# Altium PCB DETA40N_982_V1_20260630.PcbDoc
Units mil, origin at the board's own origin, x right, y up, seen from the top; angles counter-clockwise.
Board outline 2056.99 x 1054.68 mil, 4 copper layers (Top Layer, Layer 2, Layer 3, Bottom Layer), stack 62.681 mil thick; 56 components, 46 nets, 267 pads, 296 vias.
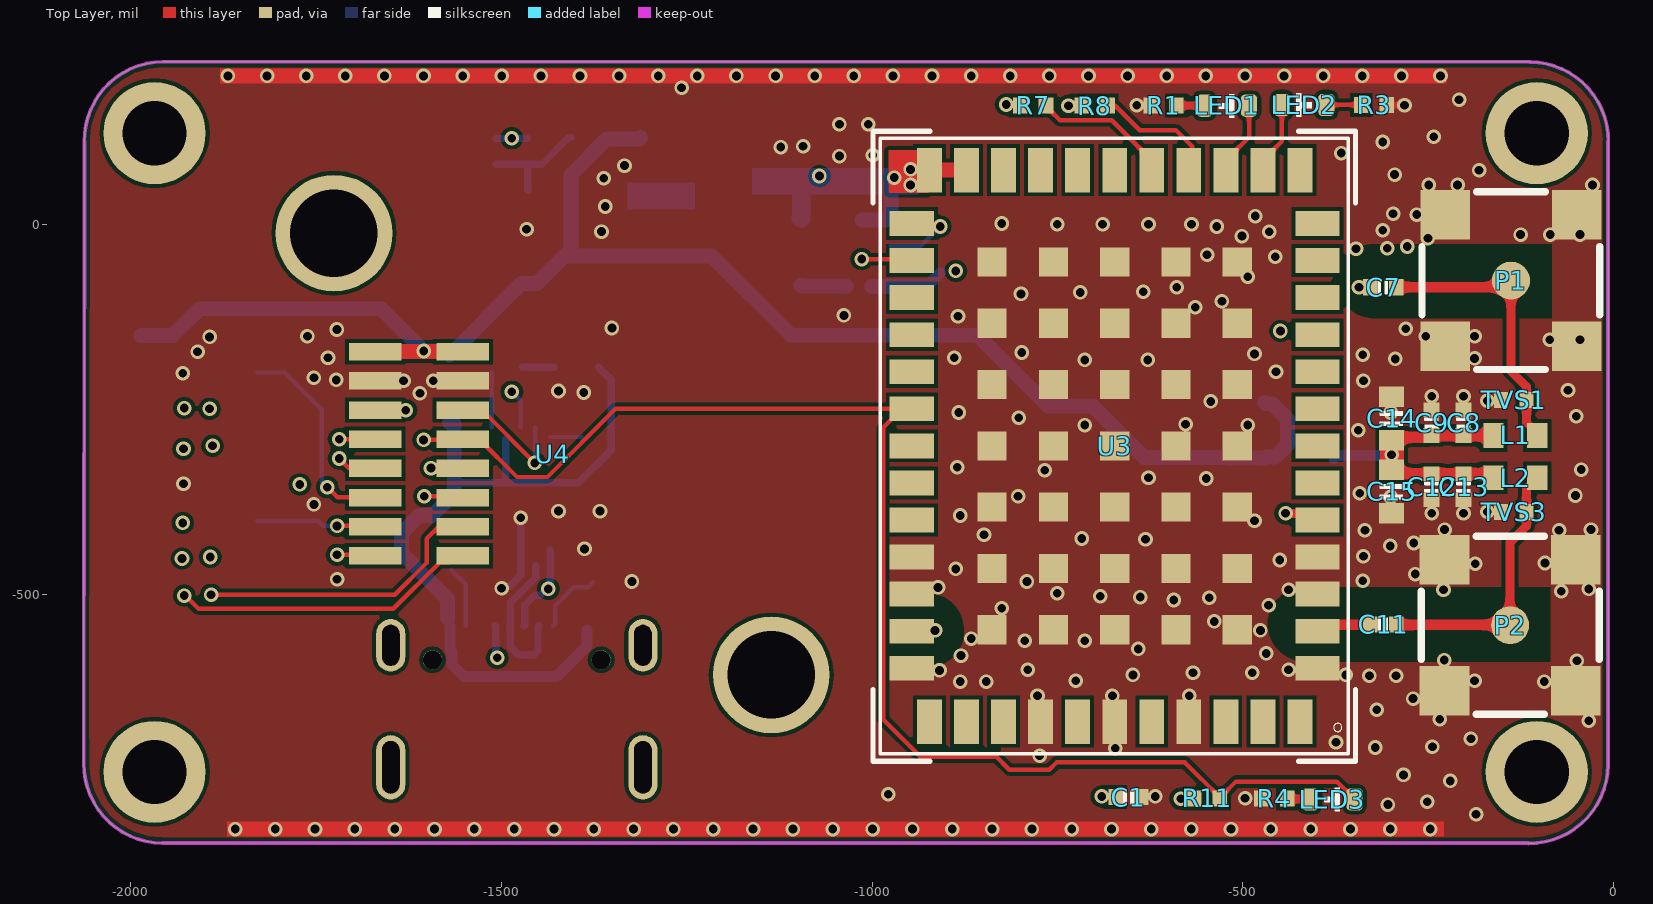
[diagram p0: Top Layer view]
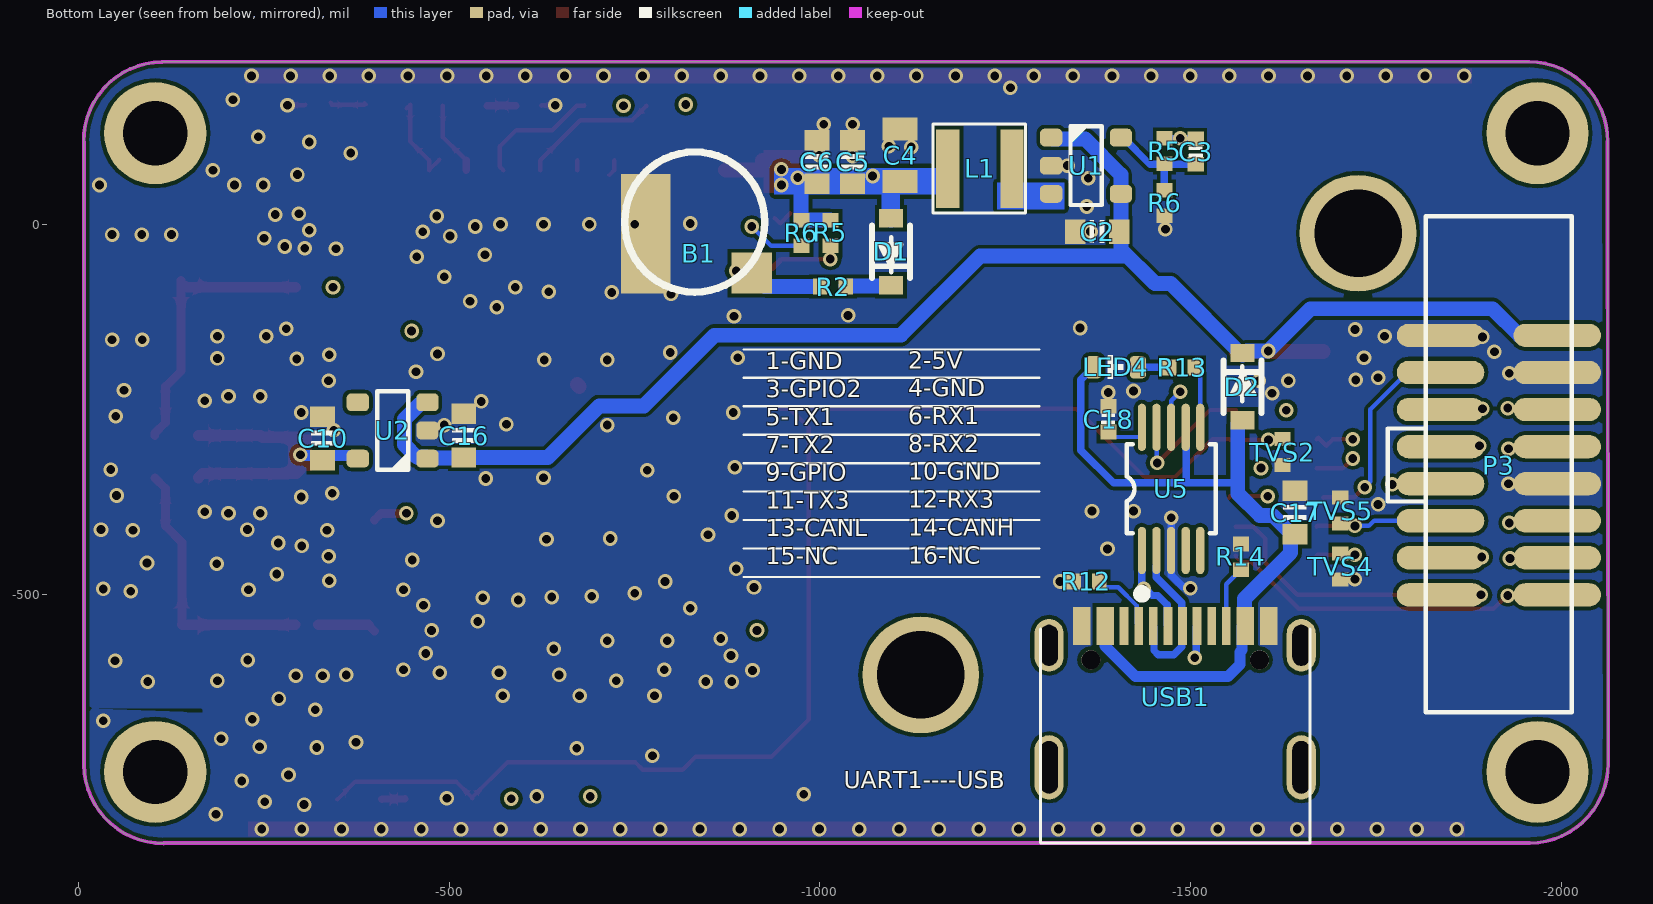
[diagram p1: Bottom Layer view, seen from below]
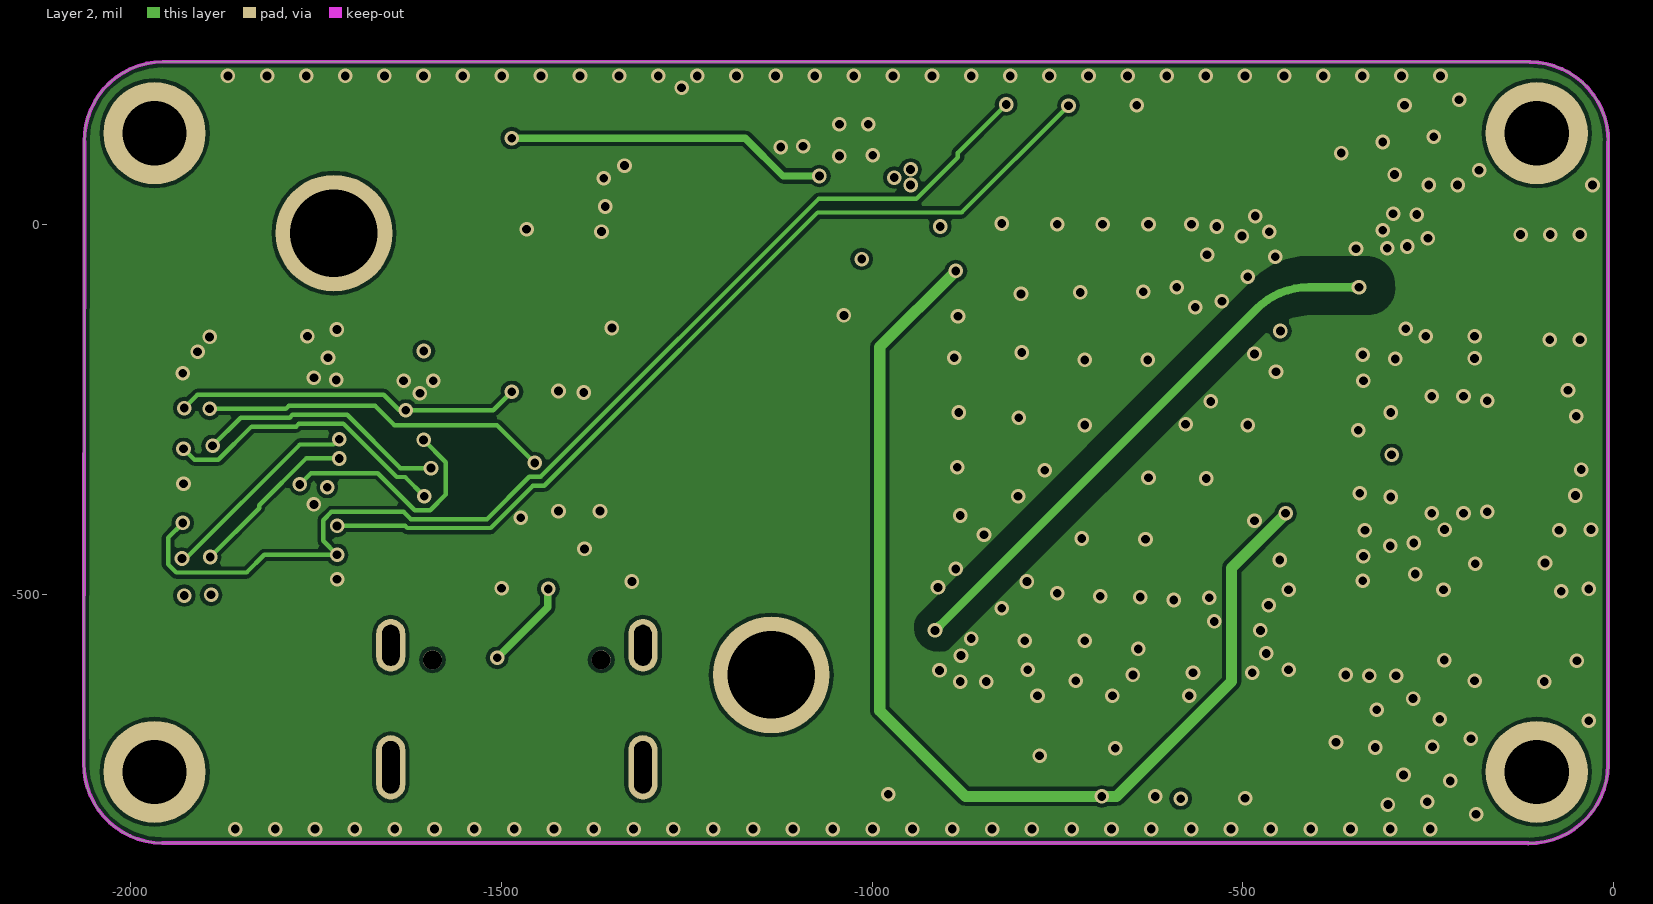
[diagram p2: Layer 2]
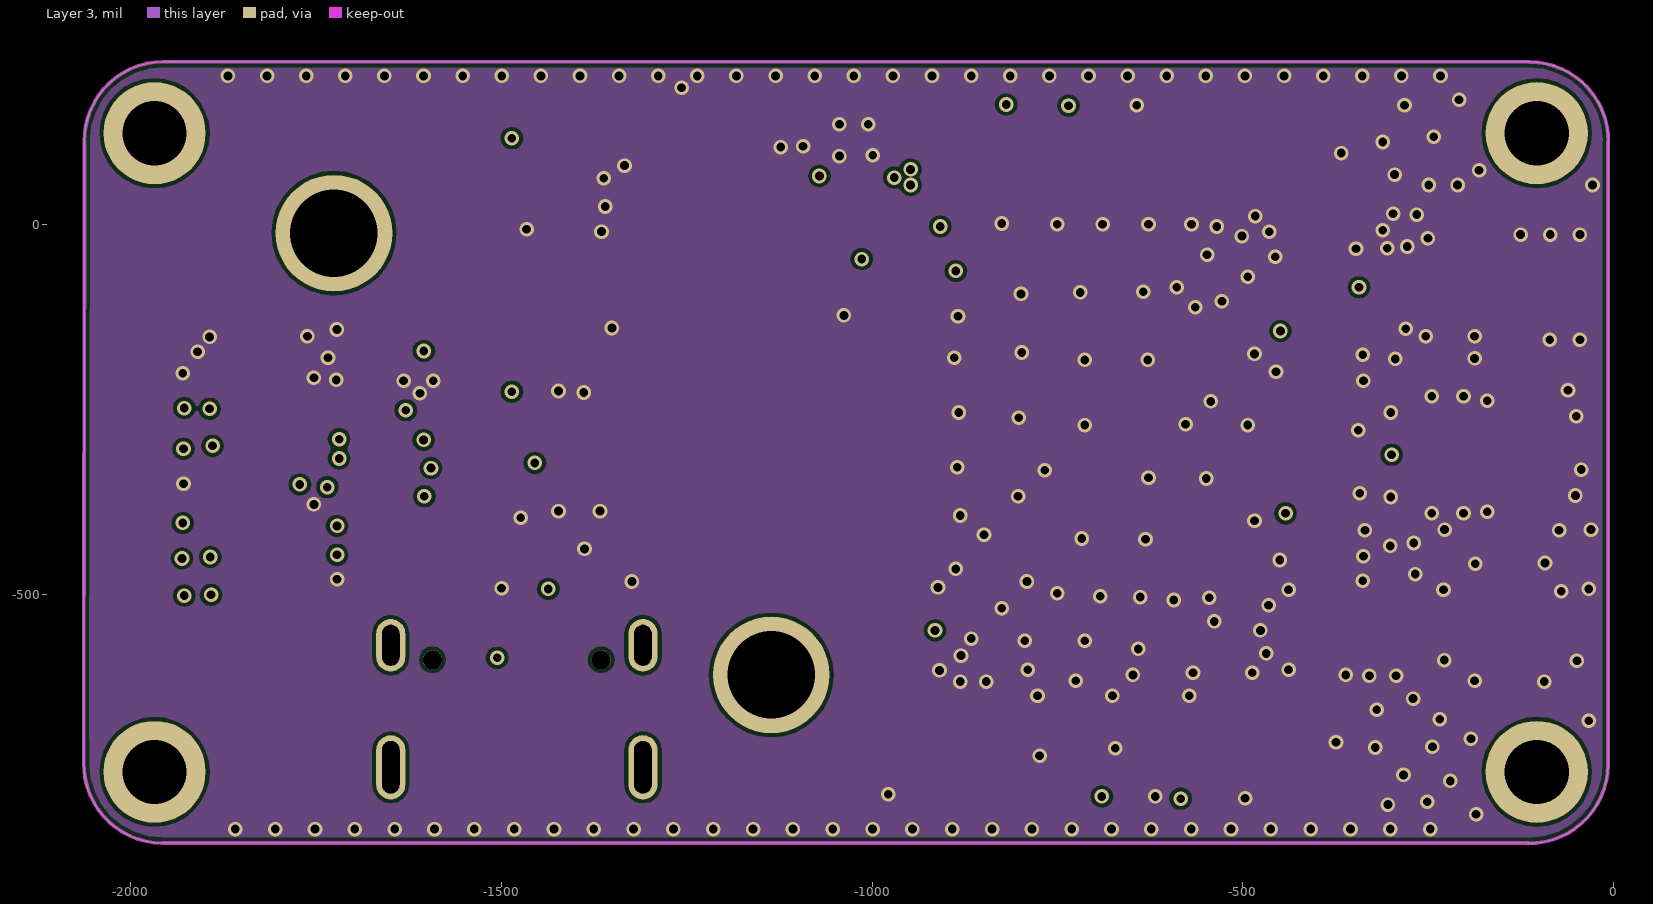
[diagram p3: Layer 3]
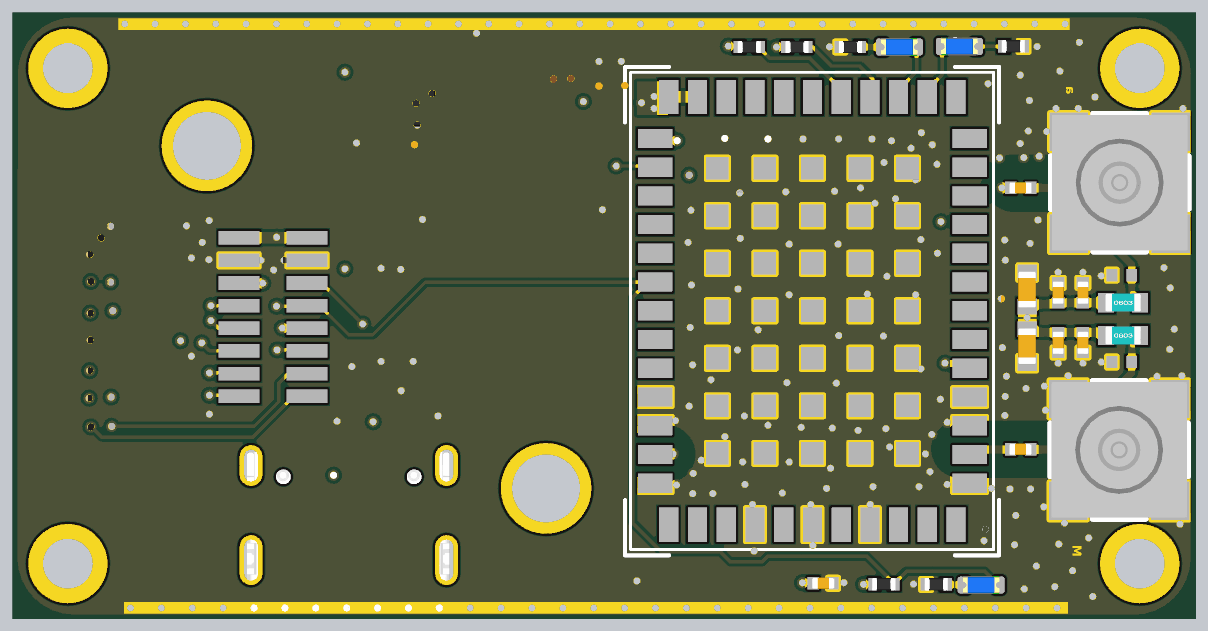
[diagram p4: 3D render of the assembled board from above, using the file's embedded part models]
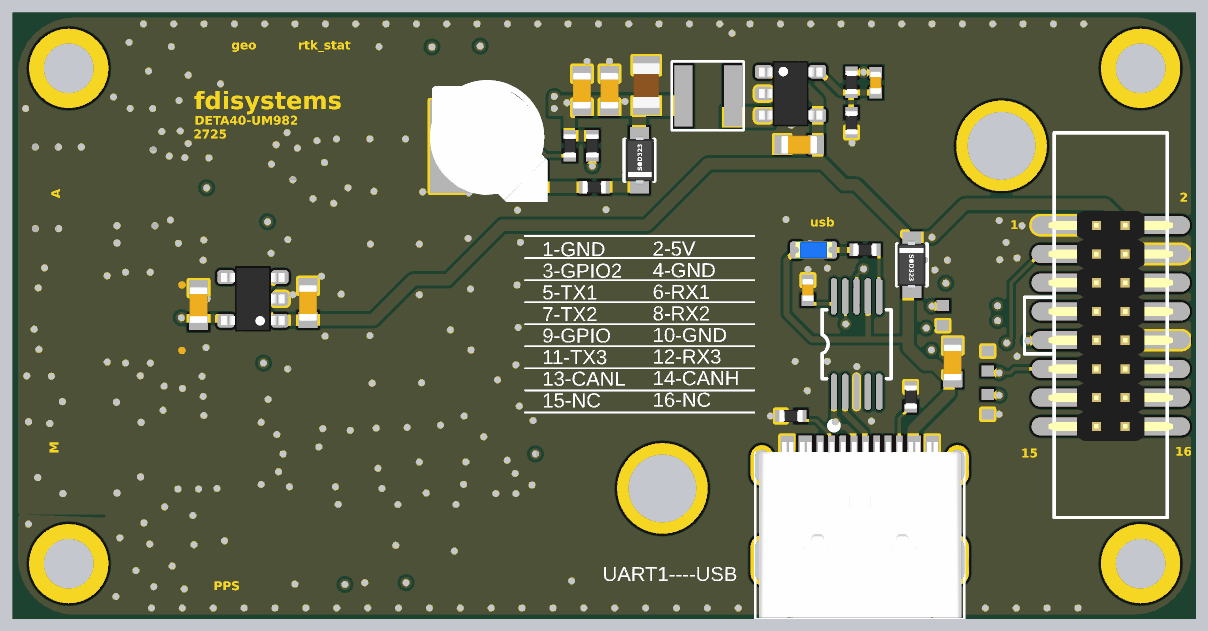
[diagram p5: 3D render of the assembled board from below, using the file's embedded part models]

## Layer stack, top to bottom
Top Solder: solder mask 0.4, Solder Resist, Dk 3.5
Top Layer: signal copper 1.4
Dielectric 2: core 17.7165, PP-006, Dk 4.2
Layer 2: signal copper 1.3778
Dielectric 4: core 19.685, Dk 4.2
Layer 3: signal copper 1.417
Dielectric 5: prepreg 19.685, Dk 4.2
Bottom Layer: signal copper 1.4
Bottom Solder: solder mask 0.4, Solder Resist, Dk 3.5

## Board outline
-2063.36,-727.39 -2063.36,-695.36 -2063.63,-695.36 -2062.68,79.68 -2062.68,111.71 cw(c-1956.04,112.67) -1957,219.31 -1957,219.12 -112.32,219.12 -112.32,219 cw(c-113.28,112.35) -6.64,111.39 -7,111.39 -7,-729.68 cw(c-113.65,-728.72) -114.61,-835.36 -114.61,-834.96 -1957.68,-834.76 -1957.68,-835 cw(c-1956.72,-728.35)

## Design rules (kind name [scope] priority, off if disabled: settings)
Clearance Clearance_1 [inpolygon] p1: gap=5 ignorepadtopadclearanceinfootprint=FALSE
Clearance [All] p2: gap=6 ignorepadtopadclearanceinfootprint=FALSE except(0: Arc-Hole Track-Hole SMDPad-Hole THPad-Hole Via-Hole Fill-Hole Poly-Hole Region-Hole Text-Hole)
DiffPairsRouting [All] p1: maxlimit=10 minlimit=10 mostfreqgap=10 toplayer_minwidth=5 toplayer_maxwidth=15 toplayer_prefwidth=15 midlayer1_minwidth=5 midlayer1_maxwidth=15 midlayer1_prefwidth=15 midlayer2_minwidth=5 midlayer2_maxwidth=15 midlayer2_prefwidth=15 bottomlayer_minwidth=5 bottomlayer_maxwidth=15 bottomlayer_prefwidth=15 maxuncoupledlength=500
PlaneConnect [All] p1: planeconnectstyle=Direct reliefexpansion=20 reliefentries=4 reliefconductorwidth=10 reliefairgap=10
PolygonConnect [All] p1: connectstyle=Direct reliefconductorwidth=10 reliefentries=4 polygonreliefangle="90 Angle" airgapwidth=10
RoutingVias [All] p1: holewidth=28 width=50 viastyle="Through Hole" minholewidth=28 minwidth=50 maxholewidth=28 maxwidth=50
SolderMaskExpansion [All] p1: expansion=4
Width [All] p1: maxlimit=100 minlimit=5 preferedwidth=10
28 further rules are at their usual default settings.

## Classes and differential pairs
component class 3.FEIMA_DETA30CPU: C16 C17 C18 D2 LED4 P3 R11 R12 R13 R14 U4 U5 USB1
component class 2.ZED-F9P_1ANT: C5 C6 C7 C8 C9 C10 C11 C12 C13 C14 C15 L1 L2 P1 P2 R5 R6 R7 R8 TVS1 TVS2 TVS3 TVS4 TVS5 U2 U3
component class "1.PWR and CON": B1 B? C1 C2 C3 C4 D1 ESD? HOLE? L1 LED1 LED2 LED3 R1 R2 R3 R4 R5 R6 U1

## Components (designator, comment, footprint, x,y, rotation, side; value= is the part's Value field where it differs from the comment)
B1 "XH414" XH414 -765,-13 r180 bottom value=MS621FE-FL11E
C1 "0.1uF/16V" C0402 -654,-773 r180 top
C2 "10uF/16V" C0603 -1374,-12 r0 bottom
C3 "33PF" C0402 -1507,98 r90 bottom
C4 "47uF" C0805 -1108,93 r270 bottom
C5 "10uF" C0603 -1046,84 r270 bottom
C6 "10uF" C0603 -998,84 r270 bottom
C7 "100P/50V 0402 5%" C0402 -310.32,-85 r0 top
C8 "0.1uF/16V" C0402 -202,-267.7 r270 top
C9 "100P/50V 0402 5%" C0402 -245,-267.7 r270 top
C10 "10uF" C0603 -331,-289 r270 bottom
C11 "100P/50V 0402 5%" C0402 -310.32,-540 r0 top
C12 "0.1uF/16V" C0402 -245,-354.3 r90 top
C13 "100P/50V 0402 5%" C0402 -202,-354.3 r90 top
C14 "10uF" C0603 -297,-262 r270 top
C15 "10uF" C0603 -301,-360.53 r90 top
C16 "10uF" C0603 -521.5,-285.22 r270 bottom
C17 "10uF" C0603 -1643,-389 r270 bottom
C18 "0.1uF/16V" C0402 -1389,-263 r270 bottom
D1 "B5819W SL 1A" SOD-323 -1096,-37 r90 bottom
D2 "B5819W SL 1A" SOD-323 -1570,-219 r270 bottom
L1 "4.7uH" "铁氧体贴片电感3*3LQH3NPN - duplicate1" -1172.39,75 r180 bottom
L1 "68nH" L0603 -132,-283 r0 top
L2 "68nH" L0603 -132,-340 r0 top
LED1 "BLUE" LED_0603_BLUE -521.37,160.02 r180 top
LED2 "BLUE" LED_0603_BLUE -417,161 r0 top
LED3 "BLUE" LED_0603_BLUE -379,-776 r180 top
LED4 "BLUE" LED_0603_BLUE -1399,-193 r180 bottom
P1 "MCX-KE" MCX-SMD_KH-MCX-KE-STM -138,-76 r90 top
P2 "MCX-KE" MCX-SMD_KH-MCX-KE-STM -139,-541 r90 top
P3 "Header 8X2" "Header_SMD_1.27X8_jianniu - inv" -1916,-324 r270 bottom
R1 "1K" RES0402 -589.37,160.02 r180 top
R2 "10R" RES0402 -1000.35,-84 r180 bottom
R3 "1K" RES0402 -340,161 r0 top
R4 "1K" RES0402 -440,-775 r180 top
R5 "45.3K" RES0402 -1465,81.35 r90 bottom
R5 "10K" RES0402 -1014,-29 r90 bottom
R6 "16.2K" RES0402 -1465,11.35 r90 bottom value=10K
R6 "10K" RES0402 -975,-29 r90 bottom
R7 "100R" RES0402 -765.35,160.02 r180 top
R8 "100R" RES0402 -682.35,160.02 r180 top
R11 "100R" RES0402 -565.29,-774.51 r0 top value=1K
R12 "5.1K" RES0402 -1376.77,-482 r0 bottom
R13 "1K" RES0402 -1471.35,-193 r180 bottom
R14 "5.1K" RES0402 -1568,-466 r90 bottom
TVS1 "ESD5451N-2/TR" ESD_0402 -117,-237 r180 top
TVS2 "ESD5451N-2/TR" ESD_0402 -1624,-290 r270 bottom
TVS3 "ESD5451N-2/TR" ESD_0402 -117,-388 r180 top
TVS4 "ESD5451N-2/TR" ESD_0402 -1702,-444.35 r270 bottom
TVS5 "ESD5451N-2/TR" ESD_0402 -1702,-403.65 r90 bottom
U1 "RY3420" SOT23-5 -1359,79 r180 bottom
U2 "RT9013-33GB" SOT23-5 -423.5,-278.22 r0 bottom
U3 "UM982" UM982 -837.98,-547.03 r90 top
U4 "FDIsystems_DETA10/20/30/40" DETA40 -1431,-310 r270 top
U5 "CH340E" MSOP-10_L3.0-W3.0-P0.50-LS5.0-BL-EP -1473.77,-357 r180 bottom
USB1 "Type-C" Type-C_Socket_16P -1295.84,-831.65 r90 bottom

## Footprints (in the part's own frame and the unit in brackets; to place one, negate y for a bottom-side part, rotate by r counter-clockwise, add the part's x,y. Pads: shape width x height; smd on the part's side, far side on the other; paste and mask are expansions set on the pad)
C0402 [mm]
  rect 0.5x0.55 smd: 1(-0.44,0) 2(0.44,0)
  silkscreen extent -0.17,-0.23 0.16,0.23, body extent -0.51,-0.25 0.49,0.25, height 0.5
C0603 [mm]
  rect 0.7x0.85 smd: 1(-0.75,-0.051) 2(0.75,-0.051)
  silkscreen extent -0.24,-0.43 0.24,0.33, body extent -0.8,-0.45 0.8,0.35, height 0.8
C0805 [mm]
  rect 0.8x1.2 smd: 1(-0.9,0) 2(0.9,0)
  body extent -1,-0.6 1,0.6, height 0.95
DETA40 [mm]
  round 4 hole 3: 0(-7.569,-7.493) 0(7.569,7.493)
  rect 0.6x1.8 smd: 1(-3.508,-3.073) 2(-3.508,-6.073) 3(-2.508,-3.073) 4(-2.508,-6.073) 5(-1.508,-3.073) 6(-1.508,-6.073) 7(-0.508,-3.073) 8(-0.508,-6.073) 9(0.492,-3.073) 10(0.492,-6.073) 11(1.492,-3.073) 12(1.492,-6.073) 13(2.492,-3.073) 14(2.492,-6.073) 15(3.492,-3.073) 16(3.492,-6.073)
  body extent -10.65,-10.65 10.55,10.55, height 8.81
ESD_0402 [mm]
  rect 0.48x0.55 smd: 1(0,0) 2(0.88,0)
  body extent -0.2,-0.38 1.09,0.38, height 0.6
"Header_SMD_1.27X8_jianniu - inv" [mm]
  oval 0.8x3 smd: 1(-4.42,-2) 2(-4.42,2) 3(-3.15,-2) 4(-3.15,2) 5(-1.88,-2) 6(-1.88,2) 7(-0.61,-2) 8(-0.61,2) 9(0.66,-2) 10(0.66,2) 11(1.93,-2) 12(1.93,2) 13(3.2,-2) 14(3.2,2) 15(4.47,-2) 16(4.47,2)
  silkscreen extent -8.5,-3.81 8.5,2.5, body extent -5.05,-2.75 5.11,2.75, height 6.4
L0603 [mm]
  rect 0.7x0.85 smd: 1(-0.75,-0.051) 2(0.75,-0.051)
  body extent -0.8,-0.44 0.8,0.36, height 0.8
LED_0603_BLUE [mil]
  rrect50% 22x30 smd: 1(-30,0) 2(30,0)
  silkscreen extent -10,-16 10,16, body extent -32,-16 32,16, height 24
MCX-SMD_KH-MCX-KE-STM [mm]
  rect 1.7x1.7 smd: 1(-2.25,-2.25) 1(-2.25,2.25) 1(2.25,2.25) 1(2.25,-2.25)
  round 1.3 smd: 2(0,0)
  silkscreen extent -3.05,-3.05 3.05,3.05, body extent -3,-3 3,3, height 5.87
MSOP-10_L3.0-W3.0-P0.50-LS5.0-BL-EP [mm]
  oval 0.28x1.62 smd paste-100 mask+0.051: 1(-1,-2.11) 2(-0.5,-2.11) 3(0,-2.11) 4(0.5,-2.11) 5(1,-2.11) 6(1,2.11) 7(0.5,2.11) 8(0,2.11) 9(-0.5,2.11) 10(-1,2.11)
  silkscreen extent -1.52,-3.75 1.52,1.52
RES0402 [mm]
  rect 0.5x0.55 smd: 1(0,0) 2(0.88,0)
  body extent -0.09,-0.27 0.96,0.28, height 0.4
SOD-323 [mm]
  rect 0.63x0.83 smd: 1(1.15,0) 2(-1.15,0)
  silkscreen extent -0.9,-0.65 0.9,0.65, body extent -1.25,-0.64 1.25,0.61, height 0.9
SOT23-5 [mil]
  rrect50% 30x24 smd: 1(-47,38) 2(-47,0) 3(-47,-38) 4(47,-38) 5(47,38)
  silkscreen extent -21,-53 21,53, body extent -55,-57 55,57, height 57
Type-C_Socket_16P [mm]
  oval 2.2x1 hole 0.6 slot 1.8 at 0 deg: 0(2.514,-8.979) 0(2.514,-0.339)
  oval 1.8x1 hole 0.6 slot 1.4 at 0 deg: 0(6.694,-8.979) 0(6.694,-0.339)
  rect 1.3x0.3 smd: A1(7.36,-1.309) A4(7.36,-2.109) A5(7.361,-3.409) A6(7.361,-4.41) A7(7.36,-4.909) A8(7.361,-5.909) A9(7.361,-7.209) A12(7.361,-8.009) B1(7.361,-7.71) B4(7.361,-6.909) B5(7.361,-6.409) B6(7.361,-5.408) B7(7.36,-3.91) B8(7.361,-2.909) B9(7.36,-2.409) B12(7.36,-1.608)
  round 0.65 hole 0.65 unplated: ""(6.194,-7.549) ""(6.194,-1.769)
  silkscreen extent -0.09,-9.28 7.26,-0.04, body extent -0.03,-9.15 7.72,-0.2, height 3.26
UM982 [mm]
  rect 0.85x1.52 smd: 1(-1.32,-11.15) 2(-0.05,-11.15) 3(1.22,-11.15) 4(2.49,-11.15) 5(3.76,-11.15) 6(5.03,-11.15) 7(6.3,-11.15) 8(7.57,-11.15) 9(8.84,-11.15) 10(10.11,-11.15) 11(11.38,-11.15) 12(12.65,-11.15) 13(13.92,-11.15) 25(13.92,2.75) 26(12.65,2.75) 27(11.38,2.75) 28(10.11,2.75) 29(8.84,2.75) 30(7.57,2.75) 31(6.3,2.75) 32(5.03,2.75) 33(3.76,2.75) 34(2.49,2.75) 35(1.22,2.75) 36(-0.05,2.75) 37(-1.32,2.75)
  rect 1x1 smd: 1(0,0) 1(0,-2.1) 1(0,-4.2) 1(0,-6.3) 1(0,-8.4) 1(2.1,-2.1) 1(2.1,0) 1(2.1,-8.4) 1(2.1,-6.3) 1(2.1,-4.2) 1(4.2,-4.2) 1(4.2,-2.1) 1(4.2,0) 1(4.2,-8.4) 1(4.2,-6.3) 1(6.3,-4.2) 1(6.3,-2.1) 1(6.3,0) 1(6.3,-8.4) 1(6.3,-6.3) 1(8.4,-8.4) 1(8.4,-6.3) 1(8.4,-4.2) 1(8.4,-2.1) 1(8.4,0) 1(10.5,-8.4) 1(10.5,-6.3) 1(10.5,-4.2) 1(10.5,-2.1) 1(10.5,0) 1(12.6,-8.4) 1(12.6,-6.3) 1(12.6,-4.2) 1(12.6,-2.1) 1(12.6,0)
  rect 1.52x0.85 smd: 14(15.75,-10.55) 15(15.75,-9.28) 16(15.75,-8.01) 17(15.75,-6.74) 18(15.75,-5.47) 19(15.75,-4.2) 20(15.75,-2.93) 21(15.75,-1.66) 22(15.75,-0.39) 23(15.75,0.88) 24(15.75,2.15) 38(-3.15,2.15) 39(-3.15,0.88) 40(-3.15,-0.39) 41(-3.15,-1.66) 42(-3.15,-2.93) 43(-3.15,-4.2) 44(-3.15,-5.47) 45(-3.15,-6.74) 46(-3.15,-8.01) 47(-3.15,-9.28) 48(-3.15,-10.55)
  silkscreen extent -4.51,-12.45 17.08,4.08
XH414 [mm]
  rect 1.4x1.4 smd: 1(3.632,-1.346)
  rect 1.7x4.1 smd: 2(0,0)
  silkscreen extent -0.72,-1.99 4.08,2.81, body extent -0.77,-2.45 4.35,2.67, height 1.6
"铁氧体贴片电感3*3LQH3NPN - duplicate1" [mm] "铁氧体贴片电感3*3"
  rect 0.8x2.7 smd: 1(0,0) 2(2.2,0)
  silkscreen extent -0.51,-1.52 2.67,1.52, body extent -0.48,-1.5 2.64,1.5, height 1

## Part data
B1: library part MS621FE-FL11E
C1 C7 C8 C9 C11 C12 C13 C18: library part "CAP C0402 DNP"
C2: library part C1
C3 C4: library part Cap, "Capacitor"
C5 C6 C10 C14 C15 C16 C17: library part Cap1, "贴片瓷介电容"
D1: library part 1n5819ws
D2: library part "D Schottky"
L1: library part L
L1 L2: library part Inductor, "高频贴片电感"
LED1 LED2 LED3 LED4: library part 19-217-BHC-XL2M2TY-3T-AM_1, "白发蓝", Part Number=100102000023
P1 P2: library part "IPEX _Antenna", "MCX-KE 全贴片母座"
P3: "Header, 8-Pin, Dual row"
R1 R3 R4 R13: library part R, "贴片电阻，1K，5%，1/16W，0402，FH", Part Number=110120100430
R2: library part "RES 10K,5%,1/16W,0402", "RES 10K,5%,1/16W,0402", Part Number='108012200014
R5 R6 R11: library part Res1, "Resistor"
R5 R6 R7 R8: library part "RES 1K,5%,1/16W,0402CC", "贴片电阻,10R,5%,1/16w,0402,FH3,FH", Part Number=110120100130
R12 R14: library part R, "贴片电阻，5.1K，5%，1/16W，0402，FH", Part Number=110120100430
TVS1 TVS2 TVS3 TVS4 TVS5: library part Varistor_0, "双向400瓦瞬态抑制器/5V", Part Number=110130100560
U1: library part SY8088AAC
U2: library part MIC5205, "500mA Low-Noise LDO Regulator"
U4: library part FDI_DETA30AN
U5: JLCPCB Part Class="Extended Part", Manufacturer=WCH
USB1: library part "Type-C Socket", "USB 3.1  单排16PIN四脚插板(L=7.35) 一体式MD"

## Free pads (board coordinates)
  round 137.8 hole 86.61: 2(-1968,-738.88) 2(-1968,122.88) 2(-103.12,-738.88) 2(-103.12,122.88)

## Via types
v1: diameter 19.68, hole 11.81, Top Layer to Bottom Layer, tented both sides, 296 vias

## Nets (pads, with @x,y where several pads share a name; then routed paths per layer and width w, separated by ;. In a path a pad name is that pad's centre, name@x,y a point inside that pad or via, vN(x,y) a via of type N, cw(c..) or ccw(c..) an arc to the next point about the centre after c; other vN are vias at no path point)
ANT1_IN: C11.1 U3.2 | length 79.9
  Top Layer w11.55: U3.2 U3.2@-390.43,-540.43
  Top Layer w13.91: U3.2@-390.43,-540.43 -327.65,-540.43 C11.1@-322.65,-540.43
ANT2_IN: C7.1 U3.36 | length 759.5
  Layer 2 w10.87: v1(-915,-548) -481.29,-114.29 cw(c-410.58,-185) -410.58,-85 v1(-343,-85)
BACKUP: B1.1 C1.2 R2.1 U3.5 | length 1620.7
  Top Layer w12: v1@-436.53,-390.47 -407.53,-390.47 U3.5
  Layer 2 w15: v1(-887,-63) -989.66,-165.66 -989.66,-656.34 -874,-772 v1(-690,-772) -670,-772 -514.93,-616.93 -514.93,-463.94 -442,-391.01 v1(-442,-390)
  Bottom Layer w15: B1.1@-926,-84 B1.1
  Bottom Layer w20: R2.1 B1.1@-926,-84
CAN1_H: P3.14 U4.8 | length 336.7
  Top Layer w6: v1(-1719,-290) -1692.11,-290 -1683.11,-299 -1672.11,-288 U4.8
  Layer 2 w6: v1(-1931,-451) -1925.77,-451 -1771.92,-297.16 -1726.16,-297.16 v1(-1719,-290)
CAN1_L: P3.13 U4.10 | length 285.6
  Top Layer w6: v1(-1719,-316) -1705.63,-329.37 U4.10
  Layer 2 w6: v1(-1892.77,-449) -1826.9,-383.13 -1826.9,-379.25 -1763.65,-316 v1(-1719,-316)
D+: U5.1 USB1.A6 USB1.B6 | length 288.2
  Layer 2 w10: v1(-1505.77,-585) -1437.61,-516.84 -1437.61,-492.84 v1(-1436.77,-492)
  Bottom Layer w10: USB1.B6 -1507.86,-542.75 -1507.86,-580.28 -1505.77,-582.38 v1(-1505.77,-585) ; USB1.A6 -1468.56,-540.94 -1468.56,-513.64 -1455.84,-500.92 -1448.31,-500.92 -1439.39,-492 v1(-1436.77,-492) -1436.77,-489.38 -1434.4,-487.01 U5.1
D-: U5.2 USB1.A7 USB1.B7 | length 202.2
  Bottom Layer w10: U5.2@-1453.77,-461 -1453.77,-476.22 -1488.21,-510.66 -1488.21,-540.99 USB1.A7 -1488.21,-542.8 -1488.21,-570.16 -1477.37,-581 -1456.53,-581 -1450.67,-575.14 -1450.67,-542.8 USB1.B7
GEOFENCE_STAT: LED2.1 U3.15 | length 124.6
  Top Layer w6: U3.15@-486.35,86.78 U3.15 -472.62,86.24 -447,111.86 LED2.1 LED2.1@-442.35,156.35
GND: B1.2 C1.1 C2.2 C4.1 C5.1 C6.1 C8.1 C9.1 C10.1 C12.1 C13.1 C14.1 C15.1 C16.1 C17.1 C18.1 P1.1 P2.1 P3.1 P3.4 P3.10 R1.2 R3.2 R4.2 R6.1@-1465,11.35 R12.2 R14.2 TVS1.2 TVS2.2 TVS3.2 TVS4.2 TVS5.2 U1.2 U2.2 U3.1 U3.3 U3.4 U3.34 U3.35 U3.37 U3.41 U3.43 U3.45 U4.3 U4.4 U5.3 USB1.A1 USB1.A12 USB1.B1 USB1.B12 | length 162.9
  Top Layer w6: v1@-645,160.65 -644.69,160.33 -624.33,160.33 R1.2 ; v1@-499.29,-774.88 -498.92,-774.51 v1(-496.66,-774.51) v1@-496.85,-774.7 ; R3.2 -305.17,160.81 -281.82,160.81 v1(-281.63,160.63)
  Top Layer w20: U3.1@-675.3,-219 U3.1@-672.62,-216.32
  Bottom Layer w10: v1(-1499.77,-491) -1497.91,-489.15 -1489.32,-489.15 -1473.77,-473.59 U5.3 -1473.88,-439.95 -1473.88,-396.12 v1(-1474,-396)
  other v1: -1859,-816 -1805.27,-816 -1751.53,-816 -1697.8,-816 -1644.07,-816 -1590.33,-816 -1536.6,-816 -1482.87,-816 -1429.13,-816 -1375.4,-816 -1321.67,-816 -1267.93,-816 -1214.2,-816 -1160.47,-816 -1106.73,-816 -1053,-816 -999.27,-816 -945.53,-816 -891.8,-816 -838.07,-816 -784.33,-816 -730.6,-816 -676.87,-816 -623.13,-816 -569.4,-816 -515.67,-816 -461.93,-816 -408.2,-816 -354.47,-816 -300.73,-816 -247,-816 -185,-796 -304,-783 -251,-779 -618,-772 -978,-769 -220,-751 -283,-743 -774,-717 -672,-707 -321,-706 -244,-705 -374,-699 -192,-694 -33,-670 -234,-668 -319,-655 -270,-640 -776.81,-636 -675.66,-636 -572,-636 -881,-617 -846,-617 -93,-617 -725,-616 -187,-616 -329,-609 -293,-609 -648,-608 -361,-608 -567,-605 -487,-605 -909,-602 -790,-601 -438,-601 -49,-589 -228,-588 -880,-582 -468,-579 -641,-573 -794,-562 -713,-562 -866,-559 -476,-548 -538.28,-535.9 -825,-518 -465,-514 -593,-507 -545,-504 -638,-503 -692,-501.74 -750,-498 -70,-495 -438,-493 -229,-493 -33,-492 -911,-490 -1324,-482 -791,-482 -338,-481 -1721.77,-479 -267,-472 -887,-465 -186,-458 -92,-457 -450,-453 -337,-448 -1388,-438 -301,-434 -269,-430 -631,-425 -717,-424 -849,-419 -335,-413 -73,-413 -227.58,-412 -30,-412 -484,-400 -881,-393 -245,-390 -202,-390 -170,-388 -1423,-387 -1367,-387 -1753,-378 -300,-368 -803,-367 -51,-366 -342,-363 -1929,-350 -549,-343 -627,-342 -767,-332 -43,-331 -885,-328 -344,-278 -713,-271 -493,-271 -577,-270 -802,-261 -50,-259 -883,-254 -300,-254 -543,-239 -170,-238 -245,-232 -202,-232 -1610,-228 -1389,-227 -1423,-225 -61,-224 -1632,-211 -1592,-211 -337,-211 -1722.77,-210 -1753,-207 -1930,-201 -455,-199 -713,-183 -628,-183 -294,-181.68 -187,-181 -1734,-180 -889,-180 -338,-176 -484,-175 -798,-173 -1910,-172 -85.5,-156 -45,-156 -1893.77,-152 -1761.77,-151 -253,-151 -187,-151 -1722,-142 -280,-141 -1351,-140 -884,-124 -1038,-123 -564,-112 -528,-104 -799,-94 -719,-92 -634,-91 -589,-85 -493,-71 -456,-44 -548,-41 -347,-33 -305,-32.35 -278,-30 -250,-19 -501,-16 -125,-14 -85,-14 -45,-14 -1365.03,-9.88 -464,-10 -311,-8 -1466.03,-6.88 -535,-3 -750,0 -689,0 -627,0 -569,0 -825,1 -483,11 -265,13 -297,14 -1360,24 -249,53 -210,53 -28,53 -1362,62 -295,67 -181,73 -1334.03,79.12 -1044,92 -999,93 -367,96 -1123.03,104.12 -1093.03,105.12 -311,111 -242,118 -1044,135 -1005,135 -643,160.53 -208,168 -1257,184 -1869,200.12 -1816.23,200.12 -1763.45,200.12 -1710.68,200.12 -1657.9,200.12 -1605.13,200.12 -1552.36,200.12 -1499.58,200.12 -1446.81,200.12 -1394.03,200.12 -1341.26,200.12 -1288.48,200.12 -1235.71,200.12 -1182.94,200.12 -1130.16,200.12 -1077.39,200.12 -1024.61,200.12 -971.84,200.12 -919.07,200.12 -866.29,200.12 -813.52,200.12 -760.74,200.12 -707.97,200.12 -655.2,200.12 -602.42,200.12 -549.65,200.12 -496.87,200.12 -444.1,200.12 -391.33,200.12 -338.55,200.12 -285.78,200.12 -233,200.12
GPIO: R11.1
  other v1: -583.65,-775
GPIO2: P3.3 U4.12 | length 277.1
  Top Layer w6: v1(-1735,-354.76) -1721.68,-368.09 -1679.76,-368.09 U4.12@-1679.11,-368.74
  Bottom Layer w6: P3.3@-1829.26,-200 -1792.41,-200 -1742.61,-249.8 -1742.61,-347.16 v1(-1735,-354.76)
NetC3_1: C3.1 R5.1@-1465,81.35 R6.2@-1465,46 U1.5 | length 151.4
  Bottom Layer w10: C3.1 R5.1@-1465.68,80.68 ; R6.2@-1464,46 -1464.5,46.5 -1464.5,79.5 R5.1@-1465.68,80.68 ; U1.5 -1409,117 -1445.32,80.68 R5.1@-1465.68,80.68
NetC7_2: C7.2 L1.2@-102.47,-285 P1.2 TVS1.1 | length 382.4
  Top Layer w9.04: P1.2@-147,-85 P1.2
  Top Layer w12: P1.2 -138,-198 -117,-219 TVS1.1 -117,-267.52 -102.47,-282.05 L1.2@-102.47,-285
  Top Layer w13.91: C7.2 P1.2@-147,-85
NetC8_2: C8.2 C9.2 C10.2 C12.2 C13.2 C14.2 C15.2 L1.1@-161.53,-285 L2.1 U2.5 | length 361.9
  Top Layer w15: C15.2 -293.5,-336.5 -167.03,-336.5 L2.1 ; C14.2 -294.83,-287.36 -247.34,-287.36 C9.2 ; C9.2 L1.1@-161.54,-285.01
  Bottom Layer w15: U2.5 -372.18,-311.9 -299.9,-311.9 v1(-299,-311)
NetC11_2: C11.2 L2.2 P2.2 TVS3.1 | length 367.5
  Top Layer w8.04: C11.2 C11.2@-292.5,-540.5
  Top Layer w12: P2.2@-139.5,-540.5 -139.5,-429.5 -117,-407 TVS3.1 -117,-356.53 L2.2
  Top Layer w13.91: C11.2@-292.5,-540.5 P2.2@-139.5,-540.5
NetC18_2: C18.2 U5.10 | length 52.3
  Bottom Layer w6: U5.10@-1434.4,-287.02 C18.2@-1396,-287.02 ; -1406,-287.02 C18.2@-1392.09,-287.02
NetD1_2: D1.2 R2.2 | length 62.1
  Bottom Layer w20: D1.2 -1095.1,-83.17 -1035.16,-83.17 -1035,-83.33 R2.2
NetL1_2: L1.2@-1259,75 U1.3
NetLED1_2: LED1.2 R1.1 | length 38
  Top Layer w10: R1.1 LED1.2
NetLED2_2: LED2.2 R3.1 | length 47.8
  Top Layer w6: LED2.2@-387,162 LED2.2@-386,163 ; LED2.2@-386,161 R3.1@-341,161 ; R3.1@-341,163 R3.1@-340,164
NetLED3_2: LED3.2 R4.1 | length 31.9
  Top Layer w10: R4.1@-440,-775.5 R4.1@-439.5,-775.5 ; R4.1 R4.1@-439.5,-775.5 ; LED3.2 -409.5,-775.5 R4.1@-439.5,-775.5
NetLED4_2: LED4.2 R13.1 | length 42.4
  Bottom Layer w10: R13.1 LED4.2
NetR5_1: R5.1@-1014,-29 U3.26 | length 82.5
  Top Layer w6: v1(-1014,-47) -948.24,-47 U3.26
  Top Layer w8: U3.26 U3.26@-936.4,-58.85
NetR6_1: R6.1@-975,-29 U3.25 | length 107.1
  Top Layer w6: U3.25@-959.98,14.73 U3.25 U3.25@-939.24,8
  Bottom Layer w6: R6.1@-975,-29 -934,-29 v1(-908,-3)
NetR12_1: R12.1 USB1.A5 | length 93
  Bottom Layer w6: USB1.A5 -1427.16,-538.94 -1427.16,-514.42 -1402.57,-489.83 -1383.61,-489.83 -1376.77,-482.98 R12.1
NetR13_2: R13.2 U5.6 | length 73.8
  Bottom Layer w6: U5.6@-1512.84,-273.64 R13.2@-1512.84,-199.84
NetR14_1: R14.1 USB1.B5 | length 84.1
  Bottom Layer w6: R14.1 -1548.16,-485.84 USB1.B5
RAW_RTK_RX: R8.1 U3.17 | length 171.5
  Top Layer w6: R8.1@-682.35,160.53 R8.1 -672.02,160.02 -639,127 -590,127 -568,105 -568,77.67 U3.17
RAW_RTK_TX: R7.1 U3.18 | length 187.1
  Top Layer w6: R7.1 -765.35,159.03 -746.51,140.19 -676.57,140.19 -622.62,86.24 U3.18
RTK_3V3: C3.2 C4.2 C5.2 C6.2 D1.1 L1.1@-1172.39,75 R5.2 R6.2@-975,5.65 U3.23 U3.24 | length 676.3
  Top Layer w20: U3.24@-922.62,86.24 U3.24 U3.23
  Layer 2 w10: v1(-1486.03,116.12) -1171.12,116.12 -1120.12,65.12 v1(-1071.03,65.12)
  Bottom Layer w10: C3.2 -1506.66,115.66 -1465.34,115.66 R5.2@-1465,116
  Bottom Layer w20: R5.2@-1014,5.65 -975,5.65 -974.4,5.65 -974.24,5.8 -974.24,52.43 -973.48,53.19
  Bottom Layer w25: D1.1 -1095.34,8.27 -1095.24,8.37 -1095.24,53.71 C4.2@-1094.48,54.47
  other v1: -948,53 -970,63 -948,74
RTK_RX: P3.11 R8.2 TVS5.1 U4.14 | length 1386.5
  Top Layer w6: v1(-1721.77,-407) -1671.22,-407 U4.14
  Layer 2 w6: v1(-1721.77,-407) -1629.94,-407 -1627.09,-409.84 -1514.49,-409.84 -1457.49,-352.84 -1442.22,-352.84 -1073.54,15.84 -879.17,15.84 v1(-735,160.02)
  Bottom Layer w6: P3.11@-1829.26,-400 -1747.61,-400 -1740.61,-407 v1(-1721.77,-407)
RTK_RX3: U3.28
RTK_STAT: LED1.1 U3.16 | length 99.9
  Top Layer w6: U3.16@-522.62,86.24 -491.37,117.49 LED1.1
  Top Layer w10: U3.16 U3.16@-522.62,86.24
RTK_TX: P3.12 R7.2 TVS4.1 U4.16 | length 1578.9
  Top Layer w6: v1(-1721.77,-446) -1671.59,-446 U4.16
  Layer 2 w6: v1(-1930,-403) -1930,-403.24 -1949.84,-423.08 -1949.84,-458.8 -1938.8,-469.84 -1843.84,-469.84 -1820,-446 v1(-1721.77,-446) -1740.61,-427.16 -1740.61,-399.2 -1729.57,-388.16 -1631.81,-388.16 -1622.12,-397.84 -1519.46,-397.84 -1462.46,-340.84 -1447.2,-340.84 -1072.2,34.16 -940.2,34.16 -884.06,90.29 -884.06,96.46 v1(-819,161.53)
RTK_TX3: U3.27
SWCLK: P3.16 U4.15 | length 403.9
  Top Layer w6: v1(-1928,-501) -1926.53,-501 -1908.69,-518.84 -1645.84,-518.84 -1583.29,-456.29 -1569.81,-456.29 U4.15@-1561,-447.48
SWDIO: P3.15 U4.13 | length 387.9
  Top Layer w6: v1(-1891.77,-500) -1644,-500 -1601,-457 -1601,-424.49 -1584.62,-408.11 U4.13@-1561,-408.11
TIMEPULSE: LED3.1 P3.9 R11.2 TVS2.1 U3.30 U4.7 | length 2174.6
  Top Layer w6: v1(-1605,-291) -1553,-291 U4.7 -1530,-290 -1479,-341 -1438,-341 -1346,-249 U3.30@-959.43,-249 ; U3.30 U3.30@-959.43,-249 ; R11.2 R11.2@-530.65,-773.53 ; LED3.1 -373.12,-751.88 -509,-751.88 R11.2@-530.65,-773.53 ; U3.30@-959.43,-249 -985.17,-274.73 -985.17,-667.89 -934.89,-718.16 -832.51,-718.16 -814.83,-735.84 -760.76,-735.84 -751.08,-726.16 -578.02,-726.16 R11.2@-530.65,-773.53
  Layer 2 w6: v1(-1772,-351) -1756.92,-335.92 -1667.07,-335.92 -1617.15,-385.84 -1596.2,-385.84 -1575,-364.65 -1575,-321 v1(-1605,-291)
UART2_RX: P3.8 U4.11 | length 444.6
  Top Layer w6: v1(-1604,-367) -1553.74,-367 U4.11
  Layer 2 w6: v1(-1929,-303) -1914.16,-317.84 -1881.96,-317.84 -1837.12,-273 -1777.06,-273 -1773.22,-269.16 -1713.16,-269.16 -1641.32,-341 -1630,-341 v1(-1604,-367)
UART2_TX: P3.7 U4.9 | length 341.9
  Layer 2 w6: v1(-1889.77,-299) -1851.77,-261 -1785.82,-261 -1781.98,-257.16 -1708.19,-257.16 -1636.35,-329 v1(-1595,-329)
USART1_RX: P3.6 U4.6 U5.8 | length 521.4
  Layer 2 w6: v1(-1928,-248) -1910.16,-230.16 -1658.61,-230.16 -1637.77,-251 v1(-1629,-251) -1511,-251 v1(-1486,-226)
  Bottom Layer w6: v1(-1486,-226) -1473.77,-238.24 U5.8
USART1_TX: P3.5 U4.5 U5.9 | length 656.2
  Top Layer w6: U4.5@-1561,-250.63 -1526.37,-250.63 v1(-1455,-322)
  Layer 2 w6: v1(-1893.77,-249) -1790.79,-249 -1786.95,-245.16 -1670.25,-245.16 -1644.41,-271 -1506,-271 v1(-1455,-322)
  Bottom Layer w6: v1(-1455,-322) -1454.54,-321.54 -1454.54,-274.39 U5.9
V_ANT1: U3.44
V_ANT2: U3.42
VBUS: C17.2 D2.1 LED4.1 U5.7 USB1.A4 USB1.A9 USB1.B4 USB1.B9 | length 1018.6
  Bottom Layer w10: -1559,-349 -1494,-349 ; U5.7@-1494,-290 -1494,-349 ; LED4.1 -1352,-210 -1352,-305 -1396,-349 -1494,-349
  Bottom Layer w15: USB1.B4@-1569.39,-541.85 -1569.39,-574.25 -1566.75,-576.9 -1566.75,-594.01 -1550.77,-610 -1425.77,-610 -1384.77,-569 USB1.A4@-1384.77,-547.8
  Bottom Layer w20: USB1.B4@-1572.77,-532 -1572.77,-505.24 -1635,-443 -1635,-417 -1610.84,-392.84 -1593.3,-392.84 -1563.66,-363.21 -1563.66,-269.68 -1566.06,-267.28 D2.1@-1570,-267.28
VDD_5V: C2.1 C16.2 D2.2 P3.2 U1.1 U1.4 U2.1 U2.3 U4.1 U4.2 | length 2182.9
  Top Layer w20: U4.2@-1679.11,-171.89 U4.1@-1561,-171.89
  Bottom Layer w20: P3.2@-1986.74,-150 -1943.43,-150 -1907.43,-114 -1661.77,-114 v1(-1604.77,-171) -1575.72,-171 -1570,-176.72 -1473.28,-80 -1452,-80 -1406,-34 U1.4 -1406,67 -1358,115 -1314,115 U1.1 ; -1412,-43 -1215.97,-43 -1109.13,-149.84 -857.7,-149.84 -762.39,-245.16 -702.3,-245.16 -632.71,-314.75 C16.2 -518.76,-315.48 -471.24,-315.48 U2.1 -468.5,-314.22 -456.22,-314.22 -439.5,-297.5 -439.5,-263.11 -460.39,-242.22 -468.5,-242.22 U2.3
pads on no net: U2.4 U3.6 U3.7 U3.8 U3.9 U3.10 U3.11 U3.12 U3.13 U3.14 U3.19 U3.20 U3.21 U3.22 U3.29 U3.31 U3.32 U3.33 U3.38 U3.39 U3.40 U3.46 U3.47 U3.48 U4.0 U5.4 U5.5 USB1. USB1.0 USB1.A8 USB1.B8
copper on no net: | length 35.7
  Top Layer w6: -722.62,86.24 -722.62,73.05 -716,66.43 ; -672.62,73.05 -672.62,86.24
  other v1: -449,-144

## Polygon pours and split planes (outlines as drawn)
GND on Top Layer (solid, remove dead copper, pour order 582): -2300,314 31,314 78,267 78,-912 -8,-998 -2128,-998
no net on Top Layer "Top Layer-No Net 5" (solid, remove dead copper, pour order 554): -1011,-924
no net on Top Layer "Top Layer-No Net 6" (solid, remove dead copper, pour order 552): -944,-876
GND on Top Layer "Top Layer-GND 17" (solid, remove dead copper, pour order 400): -953,-914
GND on Top Layer "Top Layer-GND 18" (solid, remove dead copper, pour order 398): -971,325
GND on Top Layer "Top Layer-GND 14" (solid, remove dead copper, pour order 364): -949,-878
GND on Top Layer "Top Layer-GND 15" (solid, remove dead copper, pour order 350): -976,249
GND on Top Layer "Top Layer-GND 12" (hatched Horizontal grid 6 track 6, remove dead copper, pour order 234): -1836,319
no net on Top Layer "Top Layer-No Net 4" (hatched Horizontal grid 6 track 6, remove dead copper, pour order 232): -1843,349
GND on Top Layer "Top Layer-GND 6" (hatched Horizontal grid 3.94 track 3.94, remove dead copper, pour order 138): -944,-884
no net on Top Layer "NONET_L01_P-001" (solid, remove dead copper, pour order 38): -1528,-288.88
GND on Top Layer "NONET_L01_P-001" (solid, remove dead copper, pour order 4): -2487,-221.88
GND on Top Layer "Top Layer-GND 1" (hatched Horizontal grid 3.94 track 3.94, remove dead copper, pour order 64): -964,268
no net on Top Layer "Top Layer-No Net" (hatched Horizontal grid 3.94 track 3.94, remove dead copper, pour order 74): -956,297
GND on Top Layer "Top Layer-GND 4" (hatched Horizontal grid 3.94 track 3.94, remove dead copper, pour order 84): -956,348
GND on Top Layer "Top Layer-GND 3" (hatched Horizontal grid 3.94 track 3.94, remove dead copper, pour order 94): -956,348
GND on Top Layer "Top Layer-GND 2" (hatched Horizontal grid 3.94 track 3.94, remove dead copper, pour order 108): -935,-883
GND on Top Layer "Top Layer-GND" (hatched Horizontal grid 3.94 track 3.94, remove dead copper, pour order 110): -935,-883
no net on Top Layer "Top Layer-No Net 2" (hatched Horizontal grid 6 track 6, remove dead copper, pour order 146): -937,274
no net on Top Layer "Top Layer-No Net 1" (hatched Horizontal grid 6 track 6, remove dead copper, pour order 148): -963,280
GND on Top Layer "Top Layer-GND 10" (hatched Horizontal grid 6 track 6, remove dead copper, pour order 158): -958,318
GND on Top Layer "Top Layer-GND 9" (hatched Horizontal grid 6 track 6, remove dead copper, pour order 160): -937,274
GND on Top Layer "Top Layer-GND 8" (hatched Horizontal grid 6 track 6, remove dead copper, pour order 172): -951,289
GND on Top Layer "Top Layer-GND 7" (hatched Horizontal grid 6 track 6, remove dead copper, pour order 174): -937,-896
no net on Top Layer "Top Layer-No Net 3" (hatched Horizontal grid 6 track 6, remove dead copper, pour order 186): -947,-903
GND on Top Layer "Top Layer-GND 11" (hatched Horizontal grid 6 track 6, remove dead copper, pour order 204): -963,310
GND on Layer 3 (solid, remove dead copper, pour order 586): -2178,290 -2156,312 111,312 111,-827 76,-862 -2102,-862 -2187,-777
no net on Layer 3 "NONET_L01_P-001" (solid, remove dead copper, pour order 6): -1188,235.12
GND on Layer 3 "Signal Layer 1-GND 1" (hatched Horizontal grid 3.94 track 3.94, remove dead copper, pour order 56): -1937,443
no net on Layer 3 "Signal Layer 1-No Net" (hatched Horizontal grid 6 track 6, remove dead copper, pour order 152): -1903,294
GND on Bottom Layer (solid, remove dead copper, pour order 580): -2239,347 -2226,334 133,334 54,255 54,-1030 -2007,-1030 -2160,-877
no net on Bottom Layer "Bottom Layer-No Net" (solid, remove dead copper, pour order 270): -942,-874
GND on Layer 2 (solid, remove dead copper, pour order 584): -2193,338 -2189,334 15,334 15,-954 32,-971 -67,-1070 -2202,-1070
no net on Layer 2 "Layer 2-No Net" (solid, remove dead copper, pour order 496): -1243,308

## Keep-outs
Keep-Out Layer:
  lines w5: -2063.63,-695.36 -2062.68,79.68 -2062.68,111.71 cw(c-1956.04,112.67) -1957,219.31 ; -2063.36,-695.36 -2063.36,-727.39 ccw(c-1956.72,-728.35) -1957.68,-835 ; -1957.68,-834.76 -114.61,-834.96 ; -1957,219.12 -112.32,219.12 ; -114.61,-835.36 ccw(c-113.65,-728.72) -7,-729.68 -7,111.39 ; -112.32,219 cw(c-113.28,112.35) -6.64,111.39

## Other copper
Top Layer:
  rectangle net RTK_3V3: -978,42 -924,100
  rectangle net NetC8_2: -315,-333.08 -282.39,-284
  rectangle net GND: -1870,-826 -228,-806
  rectangle net GND: -1880,190 -225,210
  pour cut-out: -83,-27 -324,-27 ccw(c-324,-76) -373,-76 ccw(c-322,-76) -322,-127 -83,-127
  pour cut-out: -927,-597.59 -925,-597.59 ccw(c-925,-548.59) -876,-548.59 ccw(c-927,-548.59) -927,-497.59
  pour cut-out: -928.74,-500 -938,-500 ccw(c-938,-549) -987,-549 ccw(c-936,-549) -928.74,-599.48
  pour cut-out: -85,-490 -417,-490 ccw(c-417,-539) -466,-539 ccw(c-415,-539) -415,-590 -85,-590
Layer 2:
  pour cut-out: -412.76,-43.18 ccw(c-412.77,-143.17) -483.47,-72.47 -935.95,-524.95 ccw(c-917.96,-542.64) -943.18,-543.18 ccw(c-910.21,-543.79) -897.44,-574.2 ccw(c-908.75,-559.37) -895.53,-572.53 -474.47,-151.47 cw(c-403.76,-222.18) -403.76,-122.18 -330.18,-122.18 ccw(c-330.18,-86.18) -294.47,-81.66 ccw(c-332.95,-81.66) -332.95,-43.18
Bottom Layer:
  rectangle net NetL1_2: -1330,20 -1239,56
  rectangle net RTK_3V3: -1162,40 -938,76
  pour cut-out: -11,-653 -165,-653 -167,-655 -167,-659
  region: -1459.79,-734.51

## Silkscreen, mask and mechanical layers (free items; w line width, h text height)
Bottom Overlay:
  lines w3: -1296,-475.86 -897,-475.86 ; -1296,-437.48 -897,-437.48 ; -1296,-399.11 -897,-399.11 ; -1296,-360.73 -897,-360.73 ; -1296,-322.36 -897,-322.36 ; -1296,-283.98 -897,-283.98 ; -1296,-245.61 -897,-245.61 ; -1296,-207.23 -897,-207.23 ; -1296,-168.86 -897,-168.86
  text "2-5V" at -1118.97,-202.86 h40
  text "1-GND" at -927,-203.86 h40
  text "4-GND" at -1119,-240.43 h40
  text "3-GPIO2" at -927,-241.4 h40
  text "6-RX1" at -1119,-278 h40
  text "5-TX1" at -927,-279 h40
  text "8-RX2" at -1119,-315.57 h40
  text "7-TX2" at -927,-316.99 h40
  text "10-GND" at -1119,-353.14 h40
  text "9-GPIO" at -927,-354.14 h40
  text "12-RX3" at -1119,-390.69 h40
  text "11-TX3" at -927,-391.69 h40
  text "14-CANH" at -1119,-428.29 h40
  text "13-CANL" at -927,-429.26 h40
  text "16-NC" at -1119,-465.86 h40
  text "15-NC" at -927,-466.86 h40
  text "UART1----USB" at -1032,-769 h40
Top Solder:
  rectangle: -1870,-826 -228,-806
  rectangle: -1880,190 -225,210
  text "a" at -231,78 h30 r270
  text "M" at -220,-727 h30 r270
Bottom Solder:
  text "rtk_stat" at -502,156 h30
  text "geo" at -386,156 h30
  text "fdisystems" at -321,52 h60
  text "DETA40-UM982" at -322,25 h30
  text "2725" at -320,1 h30
  text "A" at -88,-103 h30 r270
  text "2" at -2036,-109 h30
  text "usb" at -1393,-152 h30
  text "1" at -1741,-157 h30
  text "M" at -85,-547 h30 r270
  text "16" at -2028,-551 h30
  text "15" at -1760,-554 h30
  text "PPS" at -355,-785 h30

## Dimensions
246,-834 to -103.12,-738.88 on Mechanical 1
-44,219 to -114.61,-834.96 on Mechanical 1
